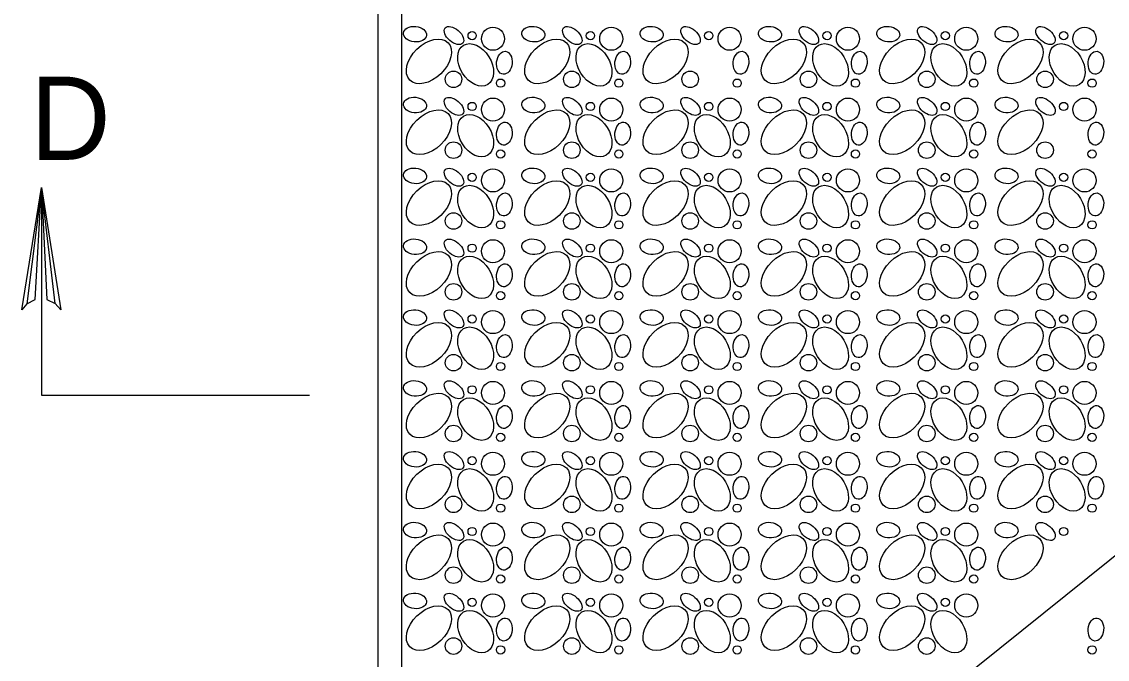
# Model space of a CAD drawing. Extents: x 636183 to 639890, y 299162 to 300538.
# Drawn here: x 637447.8 to 637504.8, y 299599.7 to 299633.1 of the extents above; entities that cross this region are included whole.
import ezdxf

# ---------------------------------------------------------------- set-up
doc = ezdxf.new("R2010")
doc.units = 0
doc.layers.add('Default', color=7, linetype='Continuous')

msp = doc.modelspace()

# ---------------------------------------------------------------- linework, layer by layer
at = {"layer": 'Default'}
for p, q in [((637448.863, 299613.522), (637462.93, 299613.522)), ((637509.082, 299608.172), (637453.503, 299563.607))]:
    msp.add_line(p, q, dxfattribs=at)
for points in [[(637466.528, 299577.98), (637564, 299577.98), (637564, 299649.515), (637466.528, 299649.515)], [(637467.774, 299579.263), (637562.439, 299579.263), (637562.439, 299647.782), (637467.774, 299647.782)]]:
    msp.add_lwpolyline(points, close=True, dxfattribs=at)
for points in [[(637448.097, 299618.313), (637448.539, 299618.541), (637448.863, 299624.416), (637448.097, 299618.313), (637447.83, 299618.001), (637448.863, 299624.416), (637449.154, 299618.546), (637449.591, 299618.331), (637448.863, 299624.416), (637449.883, 299618.001), (637449.591, 299618.331)], [(637448.863, 299624.416), (637448.863, 299613.522)]]:
    msp.add_lwpolyline(points, dxfattribs=at)
for centre, radius in [((637471.476, 299632.392), 0.217), ((637472.57, 299632.229), 0.606), ((637477.687, 299632.392), 0.217), ((637478.781, 299632.229), 0.606), ((637483.898, 299632.392), 0.217), ((637484.992, 299632.229), 0.606), ((637490.109, 299632.392), 0.217), ((637491.203, 299632.229), 0.606), ((637496.32, 299632.392), 0.217), ((637497.414, 299632.229), 0.606), ((637502.531, 299632.392), 0.217), ((637503.625, 299632.229), 0.606), ((637470.499, 299630.098), 0.435), ((637476.71, 299630.098), 0.435), ((637482.921, 299630.098), 0.435), ((637489.132, 299630.098), 0.435), ((637495.342, 299630.098), 0.435), ((637501.553, 299630.098), 0.435), ((637472.967, 299629.898), 0.217), ((637479.178, 299629.898), 0.217), ((637485.389, 299629.898), 0.217), ((637491.6, 299629.898), 0.217), ((637497.811, 299629.898), 0.217), ((637504.022, 299629.898), 0.217), ((637472.57, 299628.51), 0.606), ((637478.781, 299628.51), 0.606), ((637484.992, 299628.51), 0.606), ((637491.203, 299628.51), 0.606), ((637497.414, 299628.51), 0.606), ((637503.625, 299628.51), 0.606), ((637471.476, 299628.673), 0.217), ((637477.687, 299628.673), 0.217), ((637483.898, 299628.673), 0.217), ((637490.109, 299628.673), 0.217), ((637496.32, 299628.673), 0.217), ((637502.531, 299628.673), 0.217), ((637470.499, 299626.379), 0.435), ((637476.71, 299626.379), 0.435), ((637482.921, 299626.379), 0.435), ((637489.132, 299626.379), 0.435), ((637495.342, 299626.379), 0.435), ((637501.553, 299626.379), 0.435), ((637472.967, 299626.179), 0.217), ((637479.178, 299626.179), 0.217), ((637485.389, 299626.179), 0.217), ((637491.6, 299626.179), 0.217), ((637497.811, 299626.179), 0.217), ((637504.022, 299626.179), 0.217), ((637471.476, 299624.954), 0.217), ((637472.57, 299624.791), 0.606), ((637477.687, 299624.954), 0.217), ((637478.781, 299624.791), 0.606), ((637483.898, 299624.954), 0.217), ((637484.992, 299624.791), 0.606), ((637490.109, 299624.954), 0.217), ((637491.203, 299624.791), 0.606), ((637496.32, 299624.954), 0.217), ((637497.414, 299624.791), 0.606), ((637502.531, 299624.954), 0.217), ((637503.625, 299624.791), 0.606), ((637470.499, 299622.661), 0.435), ((637476.71, 299622.661), 0.435), ((637482.921, 299622.661), 0.435), ((637489.132, 299622.661), 0.435), ((637495.342, 299622.661), 0.435), ((637501.553, 299622.661), 0.435), ((637472.967, 299622.46), 0.217), ((637479.178, 299622.46), 0.217), ((637485.389, 299622.46), 0.217), ((637491.6, 299622.46), 0.217), ((637497.811, 299622.46), 0.217), ((637504.022, 299622.46), 0.217), ((637471.476, 299621.235), 0.217), ((637472.57, 299621.072), 0.606), ((637477.687, 299621.235), 0.217), ((637478.781, 299621.072), 0.606), ((637483.898, 299621.235), 0.217), ((637484.992, 299621.072), 0.606), ((637490.109, 299621.235), 0.217), ((637491.203, 299621.072), 0.606), ((637496.32, 299621.235), 0.217), ((637497.414, 299621.072), 0.606), ((637502.531, 299621.235), 0.217), ((637503.625, 299621.072), 0.606), ((637470.499, 299618.942), 0.435), ((637472.967, 299618.741), 0.217), ((637476.71, 299618.942), 0.435), ((637479.178, 299618.741), 0.217), ((637482.921, 299618.942), 0.435), ((637485.389, 299618.741), 0.217), ((637489.132, 299618.942), 0.435), ((637491.6, 299618.741), 0.217), ((637495.342, 299618.942), 0.435), ((637497.811, 299618.741), 0.217), ((637501.553, 299618.942), 0.435), ((637504.022, 299618.741), 0.217), ((637471.476, 299617.516), 0.217), ((637472.57, 299617.353), 0.606), ((637477.687, 299617.516), 0.217), ((637478.781, 299617.353), 0.606), ((637483.898, 299617.516), 0.217), ((637484.992, 299617.353), 0.606), ((637490.109, 299617.516), 0.217), ((637491.203, 299617.353), 0.606), ((637496.32, 299617.516), 0.217), ((637497.414, 299617.353), 0.606), ((637502.531, 299617.516), 0.217), ((637503.625, 299617.353), 0.606), ((637470.499, 299615.223), 0.435), ((637476.71, 299615.223), 0.435), ((637482.921, 299615.223), 0.435), ((637489.132, 299615.223), 0.435), ((637495.342, 299615.223), 0.435), ((637501.553, 299615.223), 0.435), ((637472.967, 299615.023), 0.217), ((637479.178, 299615.023), 0.217), ((637485.389, 299615.023), 0.217), ((637491.6, 299615.023), 0.217), ((637497.811, 299615.023), 0.217), ((637504.022, 299615.023), 0.217), ((637471.476, 299613.798), 0.217), ((637472.57, 299613.635), 0.606), ((637477.687, 299613.798), 0.217), ((637478.781, 299613.635), 0.606), ((637483.898, 299613.798), 0.217), ((637484.992, 299613.635), 0.606), ((637490.109, 299613.798), 0.217), ((637491.203, 299613.635), 0.606), ((637496.32, 299613.798), 0.217), ((637497.414, 299613.635), 0.606), ((637502.531, 299613.798), 0.217), ((637503.625, 299613.635), 0.606), ((637470.499, 299611.504), 0.435), ((637472.967, 299611.304), 0.217), ((637476.71, 299611.504), 0.435), ((637479.178, 299611.304), 0.217), ((637482.921, 299611.504), 0.435), ((637485.389, 299611.304), 0.217), ((637489.132, 299611.504), 0.435), ((637491.6, 299611.304), 0.217), ((637495.342, 299611.504), 0.435), ((637497.811, 299611.304), 0.217), ((637501.553, 299611.504), 0.435), ((637504.022, 299611.304), 0.217), ((637471.476, 299610.079), 0.217), ((637472.57, 299609.916), 0.606), ((637477.687, 299610.079), 0.217), ((637478.781, 299609.916), 0.606), ((637483.898, 299610.079), 0.217), ((637484.992, 299609.916), 0.606), ((637490.109, 299610.079), 0.217), ((637491.203, 299609.916), 0.606), ((637496.32, 299610.079), 0.217), ((637497.414, 299609.916), 0.606), ((637502.531, 299610.079), 0.217), ((637503.625, 299609.916), 0.606), ((637470.499, 299607.785), 0.435), ((637476.71, 299607.785), 0.435), ((637482.921, 299607.785), 0.435), ((637489.132, 299607.785), 0.435), ((637495.342, 299607.785), 0.435), ((637501.553, 299607.785), 0.435), ((637472.967, 299607.585), 0.217), ((637479.178, 299607.585), 0.217), ((637485.389, 299607.585), 0.217), ((637491.6, 299607.585), 0.217), ((637497.811, 299607.585), 0.217), ((637504.022, 299607.585), 0.217), ((637471.476, 299606.36), 0.217), ((637472.57, 299606.197), 0.606), ((637477.687, 299606.36), 0.217), ((637478.781, 299606.197), 0.606), ((637483.898, 299606.36), 0.217), ((637484.992, 299606.197), 0.606), ((637490.109, 299606.36), 0.217), ((637491.203, 299606.197), 0.606), ((637496.32, 299606.36), 0.217), ((637497.414, 299606.197), 0.606), ((637502.531, 299606.36), 0.217), ((637470.499, 299604.067), 0.435), ((637472.967, 299603.866), 0.217), ((637476.71, 299604.067), 0.435), ((637479.178, 299603.866), 0.217), ((637482.921, 299604.067), 0.435), ((637485.389, 299603.866), 0.217), ((637489.132, 299604.067), 0.435), ((637491.6, 299603.866), 0.217), ((637495.342, 299604.067), 0.435), ((637497.811, 299603.866), 0.217), ((637472.57, 299602.478), 0.606), ((637478.781, 299602.478), 0.606), ((637484.992, 299602.478), 0.606), ((637491.203, 299602.478), 0.606), ((637497.414, 299602.478), 0.606), ((637471.476, 299602.641), 0.217), ((637477.687, 299602.641), 0.217), ((637483.898, 299602.641), 0.217), ((637490.109, 299602.641), 0.217), ((637496.32, 299602.641), 0.217), ((637470.499, 299600.348), 0.435), ((637476.71, 299600.348), 0.435), ((637482.921, 299600.348), 0.435), ((637489.132, 299600.348), 0.435), ((637495.342, 299600.348), 0.435), ((637472.967, 299600.147), 0.217), ((637479.178, 299600.147), 0.217), ((637485.389, 299600.147), 0.217), ((637491.6, 299600.147), 0.217), ((637504.022, 299600.147), 0.217)]:
    msp.add_circle(centre, radius, dxfattribs=at)
for centre, major_axis, ratio in [((637468.476, 299632.467), (0.603, -0.061), 0.672414), ((637470.524, 299632.396), (0.459, -0.397), 0.56568), ((637474.687, 299632.467), (0.603, -0.061), 0.672414), ((637476.735, 299632.396), (0.459, -0.397), 0.56568), ((637480.898, 299632.467), (0.603, -0.061), 0.672414), ((637482.945, 299632.396), (0.459, -0.397), 0.56568), ((637487.109, 299632.467), (0.603, -0.061), 0.672414), ((637489.156, 299632.396), (0.459, -0.397), 0.56568), ((637493.32, 299632.467), (0.603, -0.061), 0.672414), ((637495.367, 299632.396), (0.459, -0.397), 0.56568), ((637499.531, 299632.467), (0.603, -0.061), 0.672414), ((637501.578, 299632.396), (0.459, -0.397), 0.56568), ((637469.208, 299631.038), (1.003, 0.982), 0.641702), ((637471.661, 299630.856), (-0.638, 1.03), 0.672414), ((637475.419, 299631.038), (1.003, 0.982), 0.641702), ((637477.872, 299630.856), (-0.638, 1.03), 0.672414), ((637481.63, 299631.038), (1.003, 0.982), 0.641702), ((637487.841, 299631.038), (1.003, 0.982), 0.641702), ((637490.294, 299630.856), (-0.638, 1.03), 0.672414), ((637494.052, 299631.038), (1.003, 0.982), 0.641702), ((637496.505, 299630.856), (-0.638, 1.03), 0.672414), ((637500.263, 299631.038), (1.003, 0.982), 0.641702), ((637502.715, 299630.856), (-0.638, 1.03), 0.672414), ((637473.168, 299630.967), (0.061, 0.603), 0.672414), ((637479.379, 299630.967), (0.061, 0.603), 0.672414), ((637485.59, 299630.967), (0.061, 0.603), 0.672414), ((637491.801, 299630.967), (0.061, 0.603), 0.672414), ((637498.012, 299630.967), (0.061, 0.603), 0.672414), ((637504.222, 299630.967), (0.061, 0.603), 0.672414), ((637468.476, 299628.748), (0.603, -0.061), 0.672414), ((637470.524, 299628.677), (0.459, -0.397), 0.56568), ((637474.687, 299628.748), (0.603, -0.061), 0.672414), ((637476.735, 299628.677), (0.459, -0.397), 0.56568), ((637480.898, 299628.748), (0.603, -0.061), 0.672414), ((637482.945, 299628.677), (0.459, -0.397), 0.56568), ((637487.109, 299628.748), (0.603, -0.061), 0.672414), ((637489.156, 299628.677), (0.459, -0.397), 0.56568), ((637493.32, 299628.748), (0.603, -0.061), 0.672414), ((637495.367, 299628.677), (0.459, -0.397), 0.56568), ((637499.531, 299628.748), (0.603, -0.061), 0.672414), ((637501.578, 299628.677), (0.459, -0.397), 0.56568), ((637469.208, 299627.319), (1.003, 0.982), 0.641702), ((637475.419, 299627.319), (1.003, 0.982), 0.641702), ((637481.63, 299627.319), (1.003, 0.982), 0.641702), ((637487.841, 299627.319), (1.003, 0.982), 0.641702), ((637494.052, 299627.319), (1.003, 0.982), 0.641702), ((637500.263, 299627.319), (1.003, 0.982), 0.641702), ((637471.661, 299627.138), (-0.638, 1.03), 0.672414), ((637477.872, 299627.138), (-0.638, 1.03), 0.672414), ((637484.083, 299627.138), (-0.638, 1.03), 0.672414), ((637490.294, 299627.138), (-0.638, 1.03), 0.672414), ((637496.505, 299627.138), (-0.638, 1.03), 0.672414), ((637473.168, 299627.248), (0.061, 0.603), 0.672414), ((637479.379, 299627.248), (0.061, 0.603), 0.672414), ((637485.59, 299627.248), (0.061, 0.603), 0.672414), ((637491.801, 299627.248), (0.061, 0.603), 0.672414), ((637498.012, 299627.248), (0.061, 0.603), 0.672414), ((637504.222, 299627.248), (0.061, 0.603), 0.672414), ((637468.476, 299625.029), (0.603, -0.061), 0.672414), ((637470.524, 299624.958), (0.459, -0.397), 0.56568), ((637474.687, 299625.029), (0.603, -0.061), 0.672414), ((637476.735, 299624.958), (0.459, -0.397), 0.56568), ((637480.898, 299625.029), (0.603, -0.061), 0.672414), ((637482.945, 299624.958), (0.459, -0.397), 0.56568), ((637487.109, 299625.029), (0.603, -0.061), 0.672414), ((637489.156, 299624.958), (0.459, -0.397), 0.56568), ((637493.32, 299625.029), (0.603, -0.061), 0.672414), ((637495.367, 299624.958), (0.459, -0.397), 0.56568), ((637499.531, 299625.029), (0.603, -0.061), 0.672414), ((637501.578, 299624.958), (0.459, -0.397), 0.56568), ((637469.208, 299623.601), (1.003, 0.982), 0.641702), ((637471.661, 299623.419), (-0.638, 1.03), 0.672414), ((637475.419, 299623.601), (1.003, 0.982), 0.641702), ((637477.872, 299623.419), (-0.638, 1.03), 0.672414), ((637481.63, 299623.601), (1.003, 0.982), 0.641702), ((637484.083, 299623.419), (-0.638, 1.03), 0.672414), ((637487.841, 299623.601), (1.003, 0.982), 0.641702), ((637490.294, 299623.419), (-0.638, 1.03), 0.672414), ((637494.052, 299623.601), (1.003, 0.982), 0.641702), ((637496.505, 299623.419), (-0.638, 1.03), 0.672414), ((637500.263, 299623.601), (1.003, 0.982), 0.641702), ((637502.715, 299623.419), (-0.638, 1.03), 0.672414), ((637473.168, 299623.529), (0.061, 0.603), 0.672414), ((637479.379, 299623.529), (0.061, 0.603), 0.672414), ((637485.59, 299623.529), (0.061, 0.603), 0.672414), ((637491.801, 299623.529), (0.061, 0.603), 0.672414), ((637498.012, 299623.529), (0.061, 0.603), 0.672414), ((637504.222, 299623.529), (0.061, 0.603), 0.672414), ((637468.476, 299621.31), (0.603, -0.061), 0.672414), ((637470.524, 299621.239), (0.459, -0.397), 0.56568), ((637474.687, 299621.31), (0.603, -0.061), 0.672414), ((637476.735, 299621.239), (0.459, -0.397), 0.56568), ((637480.898, 299621.31), (0.603, -0.061), 0.672414), ((637482.945, 299621.239), (0.459, -0.397), 0.56568), ((637487.109, 299621.31), (0.603, -0.061), 0.672414), ((637489.156, 299621.239), (0.459, -0.397), 0.56568), ((637493.32, 299621.31), (0.603, -0.061), 0.672414), ((637495.367, 299621.239), (0.459, -0.397), 0.56568), ((637499.531, 299621.31), (0.603, -0.061), 0.672414), ((637501.578, 299621.239), (0.459, -0.397), 0.56568), ((637469.208, 299619.882), (1.003, 0.982), 0.641702), ((637475.419, 299619.882), (1.003, 0.982), 0.641702), ((637481.63, 299619.882), (1.003, 0.982), 0.641702), ((637487.841, 299619.882), (1.003, 0.982), 0.641702), ((637494.052, 299619.882), (1.003, 0.982), 0.641702), ((637500.263, 299619.882), (1.003, 0.982), 0.641702), ((637471.661, 299619.7), (-0.638, 1.03), 0.672414), ((637477.872, 299619.7), (-0.638, 1.03), 0.672414), ((637484.083, 299619.7), (-0.638, 1.03), 0.672414), ((637490.294, 299619.7), (-0.638, 1.03), 0.672414), ((637496.505, 299619.7), (-0.638, 1.03), 0.672414), ((637502.715, 299619.7), (-0.638, 1.03), 0.672414), ((637473.168, 299619.811), (0.061, 0.603), 0.672414), ((637479.379, 299619.811), (0.061, 0.603), 0.672414), ((637485.59, 299619.811), (0.061, 0.603), 0.672414), ((637491.801, 299619.811), (0.061, 0.603), 0.672414), ((637498.012, 299619.811), (0.061, 0.603), 0.672414), ((637504.222, 299619.811), (0.061, 0.603), 0.672414), ((637468.476, 299617.591), (0.603, -0.061), 0.672414), ((637470.524, 299617.52), (0.459, -0.397), 0.56568), ((637474.687, 299617.591), (0.603, -0.061), 0.672414), ((637476.735, 299617.52), (0.459, -0.397), 0.56568), ((637480.898, 299617.591), (0.603, -0.061), 0.672414), ((637482.945, 299617.52), (0.459, -0.397), 0.56568), ((637487.109, 299617.591), (0.603, -0.061), 0.672414), ((637489.156, 299617.52), (0.459, -0.397), 0.56568), ((637493.32, 299617.591), (0.603, -0.061), 0.672414), ((637495.367, 299617.52), (0.459, -0.397), 0.56568), ((637499.531, 299617.591), (0.603, -0.061), 0.672414), ((637501.578, 299617.52), (0.459, -0.397), 0.56568), ((637469.208, 299616.163), (1.003, 0.982), 0.641702), ((637471.661, 299615.981), (-0.638, 1.03), 0.672414), ((637475.419, 299616.163), (1.003, 0.982), 0.641702), ((637477.872, 299615.981), (-0.638, 1.03), 0.672414), ((637481.63, 299616.163), (1.003, 0.982), 0.641702), ((637484.083, 299615.981), (-0.638, 1.03), 0.672414), ((637487.841, 299616.163), (1.003, 0.982), 0.641702), ((637490.294, 299615.981), (-0.638, 1.03), 0.672414), ((637494.052, 299616.163), (1.003, 0.982), 0.641702), ((637496.505, 299615.981), (-0.638, 1.03), 0.672414), ((637500.263, 299616.163), (1.003, 0.982), 0.641702), ((637502.715, 299615.981), (-0.638, 1.03), 0.672414), ((637473.168, 299616.092), (0.061, 0.603), 0.672414), ((637479.379, 299616.092), (0.061, 0.603), 0.672414), ((637485.59, 299616.092), (0.061, 0.603), 0.672414), ((637491.801, 299616.092), (0.061, 0.603), 0.672414), ((637498.012, 299616.092), (0.061, 0.603), 0.672414), ((637504.222, 299616.092), (0.061, 0.603), 0.672414), ((637468.476, 299613.873), (0.603, -0.061), 0.672414), ((637470.524, 299613.802), (0.459, -0.397), 0.56568), ((637474.687, 299613.873), (0.603, -0.061), 0.672414), ((637476.735, 299613.802), (0.459, -0.397), 0.56568), ((637480.898, 299613.873), (0.603, -0.061), 0.672414), ((637482.945, 299613.802), (0.459, -0.397), 0.56568), ((637487.109, 299613.873), (0.603, -0.061), 0.672414), ((637489.156, 299613.802), (0.459, -0.397), 0.56568), ((637493.32, 299613.873), (0.603, -0.061), 0.672414), ((637495.367, 299613.802), (0.459, -0.397), 0.56568), ((637499.531, 299613.873), (0.603, -0.061), 0.672414), ((637501.578, 299613.802), (0.459, -0.397), 0.56568), ((637469.208, 299612.444), (1.003, 0.982), 0.641702), ((637475.419, 299612.444), (1.003, 0.982), 0.641702), ((637481.63, 299612.444), (1.003, 0.982), 0.641702), ((637487.841, 299612.444), (1.003, 0.982), 0.641702), ((637494.052, 299612.444), (1.003, 0.982), 0.641702), ((637500.263, 299612.444), (1.003, 0.982), 0.641702), ((637471.661, 299612.262), (-0.638, 1.03), 0.672414), ((637477.872, 299612.262), (-0.638, 1.03), 0.672414), ((637484.083, 299612.262), (-0.638, 1.03), 0.672414), ((637490.294, 299612.262), (-0.638, 1.03), 0.672414), ((637496.505, 299612.262), (-0.638, 1.03), 0.672414), ((637502.715, 299612.262), (-0.638, 1.03), 0.672414), ((637473.168, 299612.373), (0.061, 0.603), 0.672414), ((637479.379, 299612.373), (0.061, 0.603), 0.672414), ((637485.59, 299612.373), (0.061, 0.603), 0.672414), ((637491.801, 299612.373), (0.061, 0.603), 0.672414), ((637498.012, 299612.373), (0.061, 0.603), 0.672414), ((637504.222, 299612.373), (0.061, 0.603), 0.672414), ((637468.476, 299610.154), (0.603, -0.061), 0.672414), ((637470.524, 299610.083), (0.459, -0.397), 0.56568), ((637474.687, 299610.154), (0.603, -0.061), 0.672414), ((637476.735, 299610.083), (0.459, -0.397), 0.56568), ((637480.898, 299610.154), (0.603, -0.061), 0.672414), ((637482.945, 299610.083), (0.459, -0.397), 0.56568), ((637487.109, 299610.154), (0.603, -0.061), 0.672414), ((637489.156, 299610.083), (0.459, -0.397), 0.56568), ((637493.32, 299610.154), (0.603, -0.061), 0.672414), ((637495.367, 299610.083), (0.459, -0.397), 0.56568), ((637499.531, 299610.154), (0.603, -0.061), 0.672414), ((637501.578, 299610.083), (0.459, -0.397), 0.56568), ((637469.208, 299608.725), (1.003, 0.982), 0.641702), ((637471.661, 299608.544), (-0.638, 1.03), 0.672414), ((637475.419, 299608.725), (1.003, 0.982), 0.641702), ((637477.872, 299608.544), (-0.638, 1.03), 0.672414), ((637481.63, 299608.725), (1.003, 0.982), 0.641702), ((637484.083, 299608.544), (-0.638, 1.03), 0.672414), ((637487.841, 299608.725), (1.003, 0.982), 0.641702), ((637490.294, 299608.544), (-0.638, 1.03), 0.672414), ((637494.052, 299608.725), (1.003, 0.982), 0.641702), ((637496.505, 299608.544), (-0.638, 1.03), 0.672414), ((637500.263, 299608.725), (1.003, 0.982), 0.641702), ((637502.715, 299608.544), (-0.638, 1.03), 0.672414), ((637473.168, 299608.654), (0.061, 0.603), 0.672414), ((637479.379, 299608.654), (0.061, 0.603), 0.672414), ((637485.59, 299608.654), (0.061, 0.603), 0.672414), ((637491.801, 299608.654), (0.061, 0.603), 0.672414), ((637498.012, 299608.654), (0.061, 0.603), 0.672414), ((637504.222, 299608.654), (0.061, 0.603), 0.672414), ((637468.476, 299606.435), (0.603, -0.061), 0.672414), ((637470.524, 299606.364), (0.459, -0.397), 0.56568), ((637474.687, 299606.435), (0.603, -0.061), 0.672414), ((637476.735, 299606.364), (0.459, -0.397), 0.56568), ((637480.898, 299606.435), (0.603, -0.061), 0.672414), ((637482.945, 299606.364), (0.459, -0.397), 0.56568), ((637487.109, 299606.435), (0.603, -0.061), 0.672414), ((637489.156, 299606.364), (0.459, -0.397), 0.56568), ((637493.32, 299606.435), (0.603, -0.061), 0.672414), ((637495.367, 299606.364), (0.459, -0.397), 0.56568), ((637499.531, 299606.435), (0.603, -0.061), 0.672414), ((637501.578, 299606.364), (0.459, -0.397), 0.56568), ((637469.208, 299605.006), (1.003, 0.982), 0.641702), ((637475.419, 299605.006), (1.003, 0.982), 0.641702), ((637481.63, 299605.006), (1.003, 0.982), 0.641702), ((637487.841, 299605.006), (1.003, 0.982), 0.641702), ((637494.052, 299605.006), (1.003, 0.982), 0.641702), ((637500.263, 299605.006), (1.003, 0.982), 0.641702), ((637471.661, 299604.825), (-0.638, 1.03), 0.672414), ((637477.872, 299604.825), (-0.638, 1.03), 0.672414), ((637484.083, 299604.825), (-0.638, 1.03), 0.672414), ((637490.294, 299604.825), (-0.638, 1.03), 0.672414), ((637496.505, 299604.825), (-0.638, 1.03), 0.672414), ((637473.168, 299604.935), (0.061, 0.603), 0.672414), ((637479.379, 299604.935), (0.061, 0.603), 0.672414), ((637485.59, 299604.935), (0.061, 0.603), 0.672414), ((637491.801, 299604.935), (0.061, 0.603), 0.672414), ((637498.012, 299604.935), (0.061, 0.603), 0.672414), ((637468.476, 299602.716), (0.603, -0.061), 0.672414), ((637470.524, 299602.645), (0.459, -0.397), 0.56568), ((637474.687, 299602.716), (0.603, -0.061), 0.672414), ((637476.735, 299602.645), (0.459, -0.397), 0.56568), ((637480.898, 299602.716), (0.603, -0.061), 0.672414), ((637482.945, 299602.645), (0.459, -0.397), 0.56568), ((637487.109, 299602.716), (0.603, -0.061), 0.672414), ((637489.156, 299602.645), (0.459, -0.397), 0.56568), ((637493.32, 299602.716), (0.603, -0.061), 0.672414), ((637495.367, 299602.645), (0.459, -0.397), 0.56568), ((637469.208, 299601.288), (1.003, 0.982), 0.641702), ((637471.661, 299601.106), (-0.638, 1.03), 0.672414), ((637475.419, 299601.288), (1.003, 0.982), 0.641702), ((637477.872, 299601.106), (-0.638, 1.03), 0.672414), ((637481.63, 299601.288), (1.003, 0.982), 0.641702), ((637484.083, 299601.106), (-0.638, 1.03), 0.672414), ((637487.841, 299601.288), (1.003, 0.982), 0.641702), ((637490.294, 299601.106), (-0.638, 1.03), 0.672414), ((637494.052, 299601.288), (1.003, 0.982), 0.641702), ((637496.505, 299601.106), (-0.638, 1.03), 0.672414), ((637473.168, 299601.216), (0.061, 0.603), 0.672414), ((637479.379, 299601.216), (0.061, 0.603), 0.672414), ((637485.59, 299601.216), (0.061, 0.603), 0.672414), ((637491.801, 299601.216), (0.061, 0.603), 0.672414), ((637504.222, 299601.216), (0.061, 0.603), 0.672414)]:
    msp.add_ellipse(centre, major_axis=major_axis, ratio=ratio, dxfattribs=at)

# ---------------------------------------------------------------- texts
msp.add_text('D', height=4.372, dxfattribs=at).set_placement((637448.274, 299625.87))

doc.saveas('drawing.dxf')
